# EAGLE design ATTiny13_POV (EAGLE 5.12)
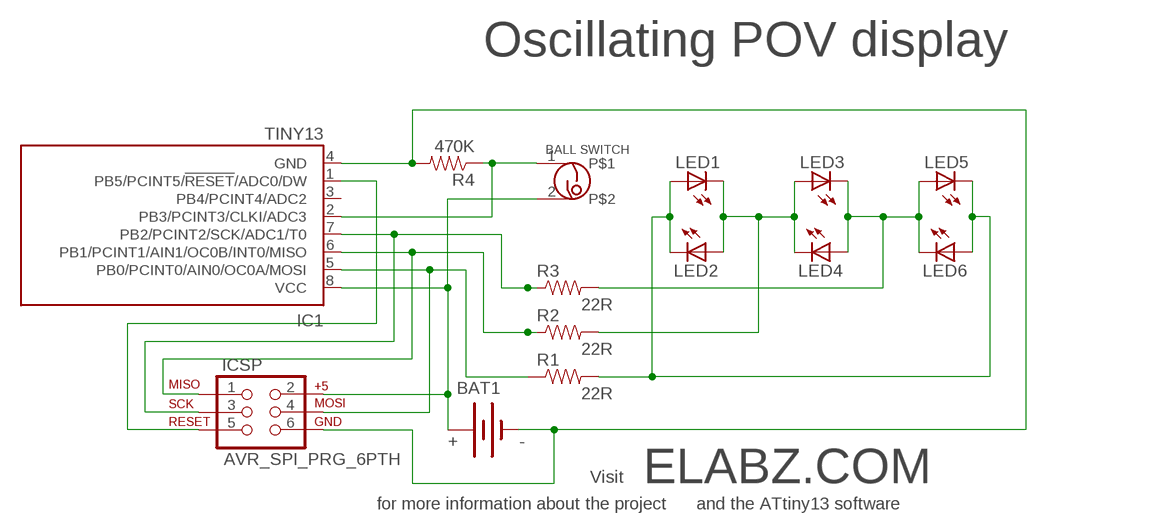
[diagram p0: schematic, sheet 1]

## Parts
BAT1  BATTERY20PTH  [BATTCOM_20MM_PTH]
IC1  TINY13  TINY13V-10SU  [8S2]
ICSP  AVR_SPI_PRG_6PTH  [2X3]
LED1  LED5MM  [LED5MM]
LED2  LED5MM  [LED5MM]
LED3  LED5MM  [LED5MM]
LED4  LED5MM  [LED5MM]
LED5  LED5MM  [LED5MM]
LED6  LED5MM  [LED5MM]
R1  22R  RESISTOR  [0805]
R2  22R  RESISTOR  [0805]
R3  22R  RESISTOR  [0805]
R4  470K  RESISTOR  [0805]
U$1  TILT SWITCH  BALL_TILT_SWITCH  [SWITCH]

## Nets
N$1: BAT1.1(+) IC1.8(VCC) ICSP.2 U$1.2
N$2: IC1.2(PB3/PCINT3/CLKI/ADC3) R4.1 U$1.1
N$3: IC1.1(PB5/PCINT5/!RESET!/ADC0/DW) ICSP.5
N$4: LED1.K(C) LED2.A LED3.A LED4.K(C) R2.2
N$5: IC1.5(PB0/PCINT0/AIN0/OC0A/MOSI) ICSP.4 R1.1
N$6: IC1.6(PB1/PCINT1/AIN1/OC0B/INT0/MISO) ICSP.1 R2.1
N$8: IC1.7(PB2/PCINT2/SCK/ADC1/T0) ICSP.3 R3.1
N$9: LED3.K(C) LED4.A LED5.A LED6.K(C) R3.2
N$10: BAT1.2(-) IC1.4(GND) ICSP.6 R4.2
N$13: LED1.A LED2.K(C) LED5.K(C) LED6.A R1.2
Unconnected: IC1.3(PB4/PCINT4/ADC2)

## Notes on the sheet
- Oscillating POV display
- + | -
- Visit | ELABZ.COM
- for more information about the project | and the ATtiny13 software

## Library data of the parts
BAT1 = SparkFun:BATTERY: Battery Holders
IC1 = atmel:TINY13: 8-bit AVR Microcontroller with 1K Bytes In-System Programmable Flash Source: http://www.atmel.com/dyn/resources/prod_documents/2535S.pdf; MPN: ATTINY13V-10SU; OC_FARNELL: 9171584; OC_NEWARK: 96K6524
ICSP = SparkFun:AVR_SPI_PRG_6: AVR ISP 6 Pin This is the reduced ISP connector for AVR programming. Common on Arduino. This footprint will take up less PCB space and can be used with a 10-pin to 6-pin adapter such as SKU: BOB-08508
LED1-LED6 = led:LED: LED
R1-R4 = SparkFun:RESISTOR: Resistor
U$1 = elabz:BALL_TILT_SWITCH

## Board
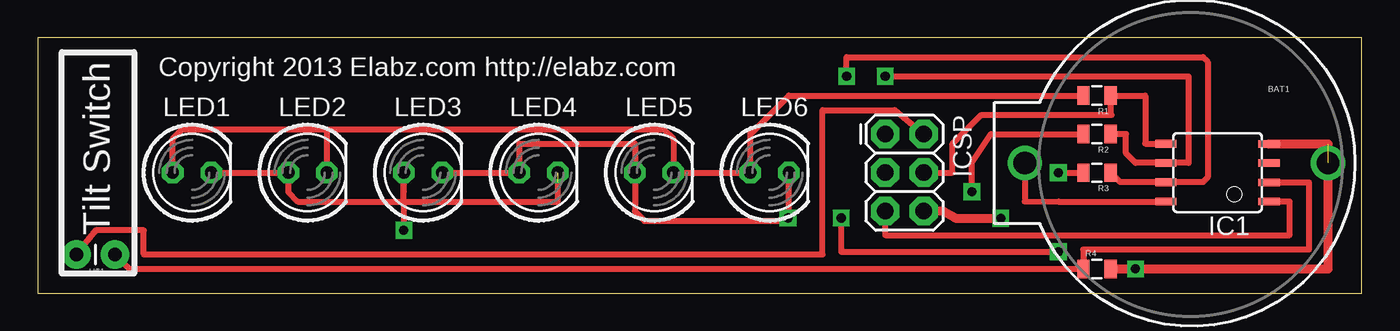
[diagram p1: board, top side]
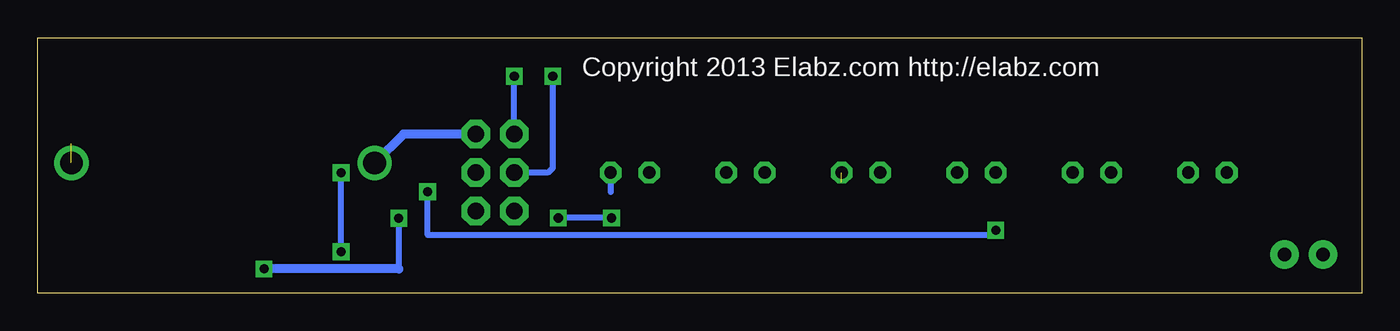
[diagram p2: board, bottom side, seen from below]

Size 87.3 x 16.82 mm. Coordinates in mm from the lower left corner, seen from the top.
Outline: 0,0 87.3,0 87.3,16.82 0,16.82 0,0
Copper layers (1*16): Top 0.035mm / dielectric 1.5mm / Bottom 0.035mm
Design rules "BatchPCB *": minimum track width 10mil, minimum drill 20mil, track to track 10mil, track to pad 10mil, pad to pad 10mil, via to via 10mil, smd to smd 10mil, copper to edge 10mil, drill to drill 10mil, minimum pad ring 12mil, minimum via ring 10mil, stop-mask expansion 4mil, vias tented up to drill 25mil, thermal gap 10mil

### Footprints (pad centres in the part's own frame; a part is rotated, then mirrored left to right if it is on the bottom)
BATTCOM_20MM_PTH = drill 1.5 round: 1 20,0; 2 0,0
8S2 = smd 0.5 x 1.4: 1 -1.905,-3.404; 2 -0.645,-3.404; 3 0.625,-3.404; 4 1.895,-3.404; 5 1.905,3.404; 6 0.635,3.404; 7 -0.635,3.404; 8 -1.905,3.404
2X3 = drill 1.1 pad 1.88 octagon: 1 0,0; 2 0,2.54; 3 2.54,0; 4 2.54,2.54; 5 5.08,0; 6 5.08,2.54
LED5MM = drill 0.813 octagon: A -1.27,0; K 1.27,0
0805 = smd 0.8 x 1.2: 1 -0.9,0; 2 0.9,0
SWITCH = drill 0.9 pad 1.88 round: 1 -1.27,0; 2 1.27,0

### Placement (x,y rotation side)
BAT1  85.09,8.57 180 top
IC1  77.79,7.94 90 top
ICSP  55.88,10.48 270 top
LED1  10.16,7.94 0 top
LED2  17.78,7.94 0 top
LED3  25.4,7.94 0 top
LED4  33.02,7.94 0 top
LED5  40.64,7.94 0 top
LED6  48.26,7.94 0 top
R1  69.85,13.02 180 top
R2  69.85,10.48 180 top
R3  69.85,7.94 180 top
R4  69.85,1.59 0 top
U$1  3.81,2.54 180 top

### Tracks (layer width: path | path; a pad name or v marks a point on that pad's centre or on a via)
N$1
  Top 0.406: IC1.8 67.31,6.03 65.09,6.04 BAT1.1 | ICSP.2 56.52,12.07 51.75,12.07 51.75,2.54 6.99,2.54 6.99,4.13 3.81,4.13 U$1.2
  Bottom 0.61: BAT1.1 63.19,10.48 ICSP.2
N$2
  Top 0.406: U$1.1 6.03,1.59 R4.1 68.95,2.86 83.82,2.86 83.82,7.29 IC1.2
N$3
  Top 0.406: IC1.1 82.55,6.03 82.55,3.81 55.88,3.81 ICSP.5
N$4  (via drill 0.6)  (1 unrouted)
  Top 0.406: LED1.K LED2.A 16.51,6.67 17.14,6.03 24.13,6.03 | 24.13,6.67 LED3.A 24.13,6.03 | R2.2 62.87,10.48 61.59,8.57 v61.59,6.67 | 24.13,6.03 v24.13,4.13 | 34.29,7.3 34.29,6.03 24.13,6.03
  Bottom 0.406: v61.59,6.67 61.59,3.81 24.13,3.81 v24.13,4.13
N$5
  Top 0.406: IC1.5 73.03,9.84 73.03,13.02 R1.1 70.75,11.8 70.8,11.75 62.23,11.75 60.33,9.84 60.33,7.94 ICSP.4
N$6  (via drill 0.6)
  Top 0.406: R2.1 71.75,10.48 71.75,9.21 72.39,8.57 IC1.6 75.88,8.57 75.88,14.29 v55.88,14.29
  Bottom 0.406: ICSP.1 v55.88,14.29
N$8  (via drill 0.6)
  Top 0.406: R3.1 71.39,7.3 IC1.7 76.83,7.3 77.15,7.62 77.15,15.24 76.83,15.56 53.34,15.56 v53.34,14.29
  Bottom 0.406: ICSP.3 53.66,7.94 53.34,8.26 v53.34,14.29
N$9  (via drill 0.6)
  Top 0.406: LED3.K LED4.A 31.75,9.84 39.37,9.84 LED5.A 39.37,5.4 40.01,4.76 48.9,4.76 49.53,5.4 | 49.53,5.4 LED6.K | v67.31,2.71 53.02,2.71 arc-90 52.98,2.76 v52.98,4.95 | 49.53,5.4 v49.47,4.95 | v67.31,7.94 R3.2
  Bottom 0.406: LED6.K 49.53,6.67 | v67.31,2.71 v67.31,7.94 | v49.47,4.95 v52.98,4.95
N$10  (via drill 0.6)  (1 unrouted)
  Top 0.61: IC1.4 85.09,9.83 | R4.2 v72.39,1.59 85.09,1.59 BAT1.2 | ICSP.6 59.69,5.4 60.5,4.93 v63.5,4.93
  Bottom 0.406: v63.5,4.93 63.5,1.59
  Bottom 0.61: 63.5,1.59 v72.39,1.59
N$13
  Top 0.406: R1.2 49.53,13.02 46.99,10.48 LED6.A LED5.K 41.91,10.16 41.27,10.79 19.05,10.79 | 19.05,10.79 9.53,10.79 8.89,10.16 LED1.A | 19.05,10.79 LED2.K

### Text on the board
tNames: Copyright 2013 Elabz.com http://elabz.com | Tilt Switch
bNames: Copyright 2013 Elabz.com http://elabz.com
